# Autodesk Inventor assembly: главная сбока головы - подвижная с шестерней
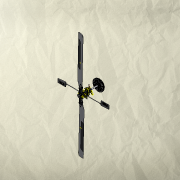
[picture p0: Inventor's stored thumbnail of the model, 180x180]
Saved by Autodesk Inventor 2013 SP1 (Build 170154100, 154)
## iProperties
Created: 2012-02
Part Number: главная сбока головы - подвижная с шестерней
Document SubType Name: Assembly
Designer: WH
ipwModelExtentsX: 971.7
ipwModelExtentsY: 196.6
ipwModelExtentsZ: 466
ipwMass: N/V
ipwArea: N/V
ipwVolume: N/V
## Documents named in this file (15)
- G:\IV2k13-Forum\Rotor\Rotor-BF.iam
- G:\IV2k13-Forum\Rotor\Koppel B - 29mm.iam
- G:\IV2k13-Forum\Rotor\Koppel C - 53mm.iam
- G:\IV2k13-Forum\Rotor\Koppel  - 24,5mm.iam
- G:\IV2k13-Forum\Rotor\Haupt-Rotorblatt.ipt
- G:\IV2k13-Forum\Rotor\Hauptrotorwelle.iam
- G:\IV2k13-Forum\Rotor\Blatthalter.iam
- G:\IV2k13-Forum\Rotor\Mischarm.iam
- G:\IV2k13-Forum\Rotor\PK-Mischarm.iam
- G:\IV2k13-Forum\Rotor\PK-Verbinder.iam
- G:\IV2k13-Forum\Rotor\Taumelscheibe.iam
- G:\IV2k13-Forum\Rotor\Taumelscheibe 2.iam
- G:\IV2k13-Forum\Rotor\PK-Zentralstueck.iam
- G:\IV2k13-Forum\Rotor\TS-Kugel.ipt
- G:\IV2k13-Forum\Rotor\Paddel mit Wippe.iam
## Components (22 placed, 15 different names)
1. Hauptrotorwelle.iam:1 [sub-assembly] — Passend:34, Fluchtend:1, Einfügen:3, Passend:33, Passend:39, Grenzwinkel Paddelwippe:13, Grenzwinkel Blatthalter 1:21, Grenzwinkel Blatthalter 2:22, Passend:63, Rotordrehung:14
2. TS-Kugel.ipt:2 — Grenzwinkel Taumelscheibe:15
3. Taumelscheibe 2.iam:3 [sub-assembly] — Passend:36, Passend:42, Einfügen:10, Passend:63, Richtungswinkel Taumelscheibe 2:23
4. Taumelscheibe.iam:4 [sub-assembly] — Passend:24, Passend:26, Passend:42, Einfügen:10, Passend:55, Passend:56, Passend:57, Grenzwinkel Taumelscheibe:15
5. PK-Verbinder.iam:5 [sub-assembly] — Passend:24, Einfügen:9
6. PK-Verbinder.iam:6 [sub-assembly] — Passend:25, Passend:26, Einfügen:8
7. PK-Mischarm.iam:7 [sub-assembly] — Passend:21, Einfügen:9, Grenzwinkel PK-Mischarm 2:4
8. PK-Mischarm.iam:8 [sub-assembly] — Passend:22, Passend:25, Einfügen:8, Grenzwinkel PK-Mischarm 1:3
9. PK-Zentralstueck.iam:9 [sub-assembly] — Passend:33, Grenzwinkel PK-Mischarm 1:3, Grenzwinkel PK-Mischarm 2:4, Passend:39
10. Koppel C - 53mm.iam:11 [sub-assembly] — Passend:54, Passend:55, Passend:56
11. Koppel C - 53mm:3 [sub-assembly] — Passend:57, Passend:58
12. Mischarm.iam:12 [sub-assembly] — Passend:45, Passend:54, Grenzwinkel Mischarm 1:16
13. Mischarm.iam:13 [sub-assembly] — Passend:44, Grenzwinkel Mischarm 2:17, Passend:58
14. Koppel B - 29mm.iam:14 [sub-assembly] — Passend:22
15. Koppel B - 29mm.iam:15 [sub-assembly] — Passend:21
16. Koppel  - 24,5mm.iam:16 [sub-assembly] — Passend:45, Passend:62
17. Koppel  - 24,5mm.iam:17 [sub-assembly] — Passend:7, Passend:44
18. Blatthalter.iam:18 [sub-assembly] — Passend:7, Grenzwinkel Blatt 1:19, Grenzwinkel Blatthalter 2:22
19. Blatthalter.iam:19 [sub-assembly] — Einfügen:3, Passend:28, Passend:29, Passend:30, Passend:62, Grenzwinkel Blatt 2:20, Grenzwinkel Blatthalter 1:21
20. Haupt-Rotorblatt.ipt:20 — Grenzwinkel Blatt 1:19
21. Haupt-Rotorblatt.ipt:21 — Passend:28, Passend:29, Passend:30, Grenzwinkel Blatt 2:20
22. Paddel mit Wippe.iam:22 [sub-assembly] — Grenzwinkel Paddelwippe:13, Grenzwinkel Mischarm 1:16, Grenzwinkel Mischarm 2:17
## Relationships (40: Mate 23, Angle 12, Insert 4, Flush 1)
- Passend:34 [Mate]: Hauptrotorwelle.iam:1
- Fluchtend:1 [Flush]: Hauptrotorwelle.iam:1
- Einfügen:3 [Insert]: Hauptrotorwelle.iam:1 ↔ Blatthalter.iam:19
- Passend:7 [Mate]: Koppel  - 24,5mm.iam:17 ↔ Blatthalter.iam:18
- Passend:21 [Mate]: PK-Mischarm.iam:7 ↔ Koppel B - 29mm.iam:15
- Passend:22 [Mate]: PK-Mischarm.iam:8 ↔ Koppel B - 29mm.iam:14
- Passend:24 [Mate]: Taumelscheibe.iam:4 ↔ PK-Verbinder.iam:5
- Passend:25 [Mate]: PK-Verbinder.iam:6 ↔ PK-Mischarm.iam:8
- Passend:26 [Mate]: Taumelscheibe.iam:4 ↔ PK-Verbinder.iam:6
- Einfügen:8 [Insert]: PK-Verbinder.iam:6 ↔ PK-Mischarm.iam:8
- Einfügen:9 [Insert]: PK-Verbinder.iam:5 ↔ PK-Mischarm.iam:7
- Passend:28 [Mate]: Blatthalter.iam:19 ↔ Haupt-Rotorblatt.ipt:21
- Passend:29 [Mate]: Blatthalter.iam:19 ↔ Haupt-Rotorblatt.ipt:21
- Passend:30 [Mate]: Blatthalter.iam:19 ↔ Haupt-Rotorblatt.ipt:21
- Passend:33 [Mate]: Hauptrotorwelle.iam:1 ↔ PK-Zentralstueck.iam:9
- Grenzwinkel PK-Mischarm 1:3 [Angle]: PK-Mischarm.iam:8 ↔ PK-Zentralstueck.iam:9
- Grenzwinkel PK-Mischarm 2:4 [Angle]: PK-Mischarm.iam:7 ↔ PK-Zentralstueck.iam:9
- Passend:36 [Mate]: Taumelscheibe 2.iam:3
- Passend:39 [Mate]: Hauptrotorwelle.iam:1 ↔ PK-Zentralstueck.iam:9
- Passend:42 [Mate]: Taumelscheibe 2.iam:3 ↔ Taumelscheibe.iam:4
- Passend:44 [Mate]: Mischarm.iam:13 ↔ Koppel  - 24,5mm.iam:17
- Passend:45 [Mate]: Mischarm.iam:12 ↔ Koppel  - 24,5mm.iam:16
- Einfügen:10 [Insert]: Taumelscheibe 2.iam:3 ↔ Taumelscheibe.iam:4
- Grenzwinkel Paddelwippe:13 [Angle]: Hauptrotorwelle.iam:1 ↔ Paddel mit Wippe.iam:22
- Passend:54 [Mate]: Koppel C - 53mm.iam:11 ↔ Mischarm.iam:12
- Passend:55 [Mate]: Taumelscheibe.iam:4 ↔ Koppel C - 53mm.iam:11
- Passend:56 [Mate]: Taumelscheibe.iam:4 ↔ Koppel C - 53mm.iam:11
- Grenzwinkel Mischarm 1:16 [Angle]: Mischarm.iam:12 ↔ Paddel mit Wippe.iam:22
- Grenzwinkel Mischarm 2:17 [Angle]: Mischarm.iam:13 ↔ Paddel mit Wippe.iam:22
- Passend:57 [Mate]: Taumelscheibe.iam:4 ↔ Koppel C - 53mm:3
- Grenzwinkel Taumelscheibe:15 [Angle]: TS-Kugel.ipt:2 ↔ Taumelscheibe.iam:4
- Passend:58 [Mate]: Koppel C - 53mm:3 ↔ Mischarm.iam:13
- Passend:62 [Mate]: Koppel  - 24,5mm.iam:16 ↔ Blatthalter.iam:19
- Grenzwinkel Blatt 1:19 [Angle]: Blatthalter.iam:18 ↔ Haupt-Rotorblatt.ipt:20
- Grenzwinkel Blatt 2:20 [Angle]: Blatthalter.iam:19 ↔ Haupt-Rotorblatt.ipt:21
- Grenzwinkel Blatthalter 1:21 [Angle]: Hauptrotorwelle.iam:1 ↔ Blatthalter.iam:19
- Grenzwinkel Blatthalter 2:22 [Angle]: Hauptrotorwelle.iam:1 ↔ Blatthalter.iam:18
- Passend:63 [Mate]: Hauptrotorwelle.iam:1 ↔ Taumelscheibe 2.iam:3
- Rotordrehung:14 [Angle]: Hauptrotorwelle.iam:1
- Richtungswinkel Taumelscheibe 2:23 [Angle]: Taumelscheibe 2.iam:3
## Named parameters: d124_d7 = 0
